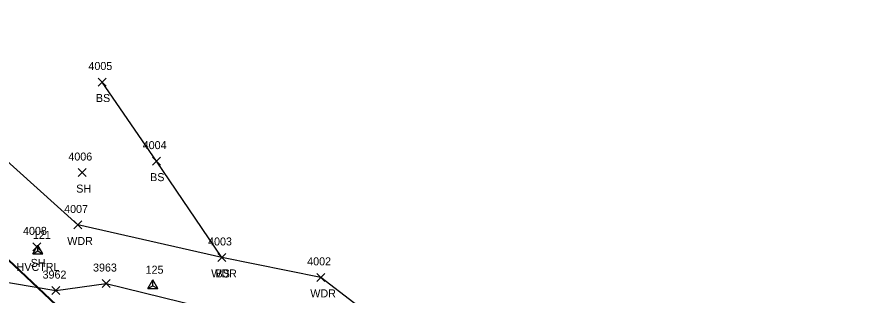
# Model space of a CAD drawing. Extents: x 1647574 to 1652703, y 212895 to 228670.
# Drawn here: x 1648896.4 to 1649108.2, y 227311.5 to 227381 of the extents above; entities that cross this region are included whole.
import ezdxf

# ---------------------------------------------------------------- set-up
doc = ezdxf.new("R2010")
doc.units = 0
for name, color, linetype in [('BDC', 7, 'Continuous'), ('C_A', 7, 'Continuous'), ('C_I', 7, 'Continuous'), ('CPSM', 7, 'Continuous'), ('L_A', 7, 'Continuous'), ('L_I', 7, 'Continuous'), ('L_TIC', 7, 'Continuous'), ('LASF', 7, 'Continuous'), ('LAWA', 7, 'Continuous'), ('LELB', 7, 'Continuous')]:
    doc.layers.add(name, color=color, linetype=linetype)

msp = doc.modelspace()

# ---------------------------------------------------------------- linework, layer by layer
at = {"layer": 'BDC'}
for points in [[(1649243.4, 226991.01), (1649194.89, 227036.57), (1649144.77, 227083.81), (1649080.19, 227144.73), (1649023.11, 227198.76), (1648965.38, 227253.07), (1648915.01, 227300.54), (1648862.79, 227349.77)], [(1649243.53, 226991.1), (1649195.07, 227036.68), (1649144.94, 227083.85), (1649080.28, 227144.79), (1649023.25, 227198.71), (1648965.39, 227253.22), (1648915.18, 227300.61), (1648862.96, 227349.86)]]:
    msp.add_lwpolyline(points, dxfattribs=at)
at = {"layer": 'CPSM'}
for p, q in [((1648900.32, 227321.81), (1648901.57, 227323.97)), ((1648900.32, 227321.81), (1648901.57, 227322.53)), ((1648902.82, 227321.81), (1648901.57, 227323.97)), ((1648901.57, 227322.53), (1648901.57, 227323.97)), ((1648901.57, 227322.53), (1648901.57, 227322.53)), ((1648901.57, 227322.53), (1648902.82, 227321.81)), ((1648900.32, 227321.81), (1648902.82, 227321.81)), ((1648929.04, 227313.11), (1648930.29, 227315.28)), ((1648931.54, 227313.11), (1648930.29, 227315.28)), ((1648930.29, 227313.83), (1648930.29, 227315.28)), ((1648929.04, 227313.11), (1648930.29, 227313.83)), ((1648929.04, 227313.11), (1648931.54, 227313.11)), ((1648930.29, 227313.83), (1648930.29, 227313.83)), ((1648930.29, 227313.83), (1648931.54, 227313.11))]:
    msp.add_line(p, q, dxfattribs=at)
at = {"layer": 'L_TIC'}
for points in [[(1648916.63, 227363.71), (1648918.63, 227365.71)], [(1648918.63, 227363.71), (1648916.63, 227365.71)], [(1648930.18, 227343.95), (1648932.18, 227345.95)], [(1648932.18, 227343.95), (1648930.18, 227345.95)], [(1648911.67, 227341.09), (1648913.67, 227343.09)], [(1648913.67, 227341.09), (1648911.67, 227343.09)], [(1648910.56, 227328), (1648912.56, 227330)], [(1648912.56, 227328), (1648910.56, 227330)], [(1648900.29, 227322.53), (1648902.29, 227324.53)], [(1648902.29, 227322.53), (1648900.29, 227324.53)], [(1648946.52, 227319.89), (1648948.52, 227321.89)], [(1648948.52, 227319.89), (1648946.52, 227321.89)], [(1648946.52, 227319.89), (1648948.52, 227321.89)], [(1648948.52, 227319.89), (1648946.52, 227321.89)], [(1648971.27, 227314.92), (1648973.27, 227316.92)], [(1648973.27, 227314.92), (1648971.27, 227316.92)], [(1648917.66, 227313.37), (1648919.66, 227315.37)], [(1648919.66, 227313.37), (1648917.66, 227315.37)], [(1648905.07, 227311.61), (1648907.07, 227313.61)], [(1648907.07, 227311.61), (1648905.07, 227313.61)]]:
    msp.add_lwpolyline(points, dxfattribs=at)
at = {"layer": 'LASF'}
msp.add_lwpolyline([(1648650.22, 227380.96), (1648665.19, 227366.23), (1648704.75, 227348.92), (1648726.24, 227345), (1648748.02, 227340.21), (1648778.69, 227335.47), (1648795.18, 227328.09), (1648829.72, 227323.98), (1648869.23, 227314.25), (1648889.74, 227315.36), (1648906.07, 227312.61), (1648918.66, 227314.37), (1648951.49, 227306.35), (1648977.57, 227292.25), (1648987.29, 227278.61), (1648987.25, 227274.74)], dxfattribs=at)
at = {"layer": 'LAWA'}
msp.add_lwpolyline([(1649036.39, 227297.45), (1649019.42, 227301.75), (1648997.01, 227296.87), (1648972.27, 227315.92), (1648947.52, 227320.89), (1648911.56, 227329), (1648891.16, 227347.34), (1648874.09, 227360.76)], dxfattribs=at)
at = {"layer": 'LELB'}
msp.add_lwpolyline([(1648947.52, 227320.89), (1648931.18, 227344.95), (1648917.63, 227364.71)], dxfattribs=at)

# ---------------------------------------------------------------- texts
at = {"layer": 'C_A'}
msp.add_text('HVCTRL', height=2, dxfattribs=at).set_placement((1648896.27, 227317.53))
at = {"layer": 'C_I'}
for s, p in [('121', (1648900.35, 227325.53)), ('125', (1648928.49, 227316.83))]:
    msp.add_text(s, height=2, dxfattribs=at).set_placement(p)
at = {"layer": 'L_A'}
for s, p in [('BS', (1648916.07, 227359.71)), ('BS', (1648929.62, 227339.95)), ('SH', (1648911.16, 227337.09)), ('WDR', (1648908.92, 227324)), ('SH', (1648899.78, 227318.53)), ('WDR', (1648944.88, 227315.89)), ('BS', (1648945.96, 227315.89)), ('WDR', (1648969.63, 227310.92))]:
    msp.add_text(s, height=2, dxfattribs=at).set_placement(p)
at = {"layer": 'L_I'}
for s, p in [('4005', (1648914.21, 227367.71)), ('4004', (1648927.77, 227347.95)), ('4006', (1648909.2, 227345.09)), ('4007', (1648908.14, 227332)), ('4008', (1648897.87, 227326.53)), ('4003', (1648944.1, 227323.89)), ('4003', (1648944.1, 227323.89)), ('4002', (1648968.85, 227318.92)), ('3963', (1648915.36, 227317.37)), ('3962', (1648902.76, 227315.61))]:
    msp.add_text(s, height=2, dxfattribs=at).set_placement(p)

doc.saveas('drawing.dxf')
